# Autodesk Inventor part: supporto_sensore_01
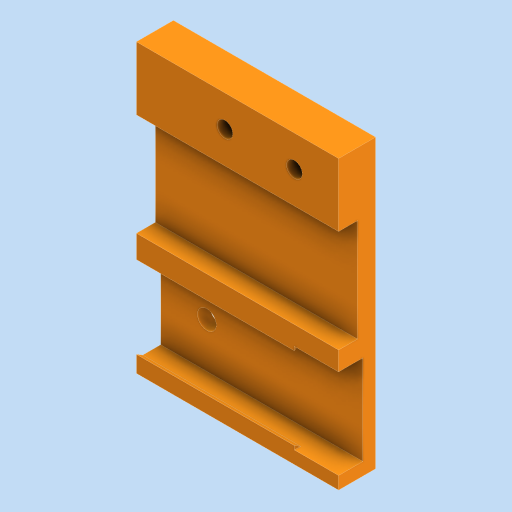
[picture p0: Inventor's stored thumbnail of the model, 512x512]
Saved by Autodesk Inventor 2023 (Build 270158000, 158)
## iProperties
Created: 2023-05
Part Number: supporto_sensore_01
Material: Generico
Document SubType Name: Modeling
Designer: x300
Density: 1 g/cm^3
Appearance: Arancione
Author: x300
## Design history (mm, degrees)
sketch "Schizzo1"
  geometry: L1 (0, 0)-(32, 0); L2 (32, 0)-(32, 18); L3 (32, 18)-(0, 18); L4 (0, 18)-(0, 0)
  constraints: 8 end point, 2 parallel, 1 horizontal, 1 perpendicular
  dimensions: "d2" = 18 distance of L1.end L2.end; "d3" = 32 distance of L1.start L1.end
extrude "Estrusione1" new body sketch "Schizzo1" distance "d0" = 2; taper "d1" = 0 deg
node "Piano di lavoro1"
sketch "Schizzo2"
  geometry: L1 (0, 2)-(32, 2) reference; L2 (32, 16.2)-(0, 16.2) reference; L3 (32, 0)-(32, 18) reference; L4 (32, 18)-(0, 18) reference; L5 (0, 18)-(0, 0) reference; L6 (0, 0)-(32, 0) reference; 5 further points
extrude "Estrusione2" join sketch "Schizzo2" stored distance "d4" = 3; taper "d5" = 0 deg
sketch "Schizzo3"
  geometry: C1 r 1.5 at (7.3, 9.1) reference; 1 further point
extrude "Estrusione3" cut sketch "Schizzo3" extent not by distance; stored distance "d6" = 0; taper "d7" = 0 deg
sketch "Schizzo4"
  geometry: L1 (32, 0)-(0, 0) reference; L2 (0, 0)-(0, -5.85) reference; L3 (32, -5.85)-(0, -5.85) reference; L4 (32, 0)-(32, -5.85) reference; 1 further point
  node "Linea chiusa proiettata2"
node "Piano di lavoro2"
extrude "Estrusione4" join sketch "Schizzo4" stored distance "d8" = 27.5; taper "d9" = 0 deg
sketch "Schizzo5"
  geometry: L1 (3.85, 14.2)-(3.85, 43.45) reference; L2 (0, 14.2)-(3.85, 14.2) reference; L3 (3.85, 33.44)-(0.85, 33.44); L4 (0.85, 33.44)-(0.85, 14.2); L5 (0.85, 14.2)-(3.85, 14.2); L6 (3.85, 14.2)-(3.85, 33.44); L7 (3.85, 14.2)-(0.85, 14.2); L8 (0.85, 14.2)-(0.85, 17.2); L9 (0.85, 17.2)-(3.85, 17.2); L10 (3.85, 17.2)-(3.85, 14.2); 2 further points
  constraints: 16 end point, 4 parallel, 3 point on line, 2 horizontal, 2 perpendicular
  dimensions: "d10" = 3 distance of L5.end L4.end; "d11" = 3 distance of L7.end L8.end
extrude "Estrusione5" cut sketch "Schizzo5" extent not by distance; stored distance "d12" = 0; taper "d13" = 0 deg
sketch "Schizzo6"
  geometry: L1 (-32, 0)-(-32, 45.45) reference; L2 (-47.6, 45.45)-(-47.6, 35.45) reference; L3 (-47.6, 40.45)-(18.035, 40.45); 3 further points
  constraints: 2 end point, 2 point on line, 1 horizontal, 1 midpoint
  dimensions: "d14" = 7 distance from line of L1 point (-25, 40.45); "d15" = 11 distance of point (-25, 40.45) point (-14, 40.45)
hole "Foro1" sketch "Schizzo6" at (-25, 40.45), (-14, 40.45) diameter "d16" = 2.5; stored, may be unused: countersink angle "d20" = 82 deg, drill point angle "d22" = 118 deg; dims "d17" = 6, "d18" = 11, "d19" = 2.6, "d21" = 8
sketch "Schizzo7"
  geometry: L1 (0, 14.2)-(3.85, 14.2) reference; L2 (3.85, 14.2)-(3.85, 13.6); L3 (3.85, 13.6)-(2.85, 14.2); L4 (2.85, 14.2)-(3.85, 14.2); L5 (0, 14.2)-(0, 0) reference; L6 (0, 7.1)-(4.736, 7.1); L7 (3.85, 0)-(3.85, 0.6); L8 (3.85, 0.6)-(2.85, 0); L9 (2.85, 0)-(3.85, 0); 2 further points
  constraints: 14 end point, 3 symmetric about line, 1 horizontal, 1 midpoint, 1 perpendicular, 1 vertical
  dimensions: "d23" = 0.6 distance of L1.end L2.end; "d24" = 1 distance of L3.end L1.end
extrude "Estrusione6" join sketch "Schizzo7" distance "d25" = 25; taper "d26" = 0 deg
sketch "Schizzo8"
  geometry: L1 (22.162, 1.084)-(5.219, 1.084); L2 (5.219, 1.084)-(5.219, 4.858); L3 (5.219, 4.858)-(22.162, 4.858); L4 (22.162, 4.858)-(22.162, 1.084); 1 further point
  constraints: 2 other
feature "Sbalzo1" sketch "Schizzo8" dims "d27" = 0.2, "d28" = 0
node "Solido1"
node "Riferimento1"
node "Riferimento2"
node "Linea chiusa proiettata1"
node "Riferimento3"
node "Riferimento4"
